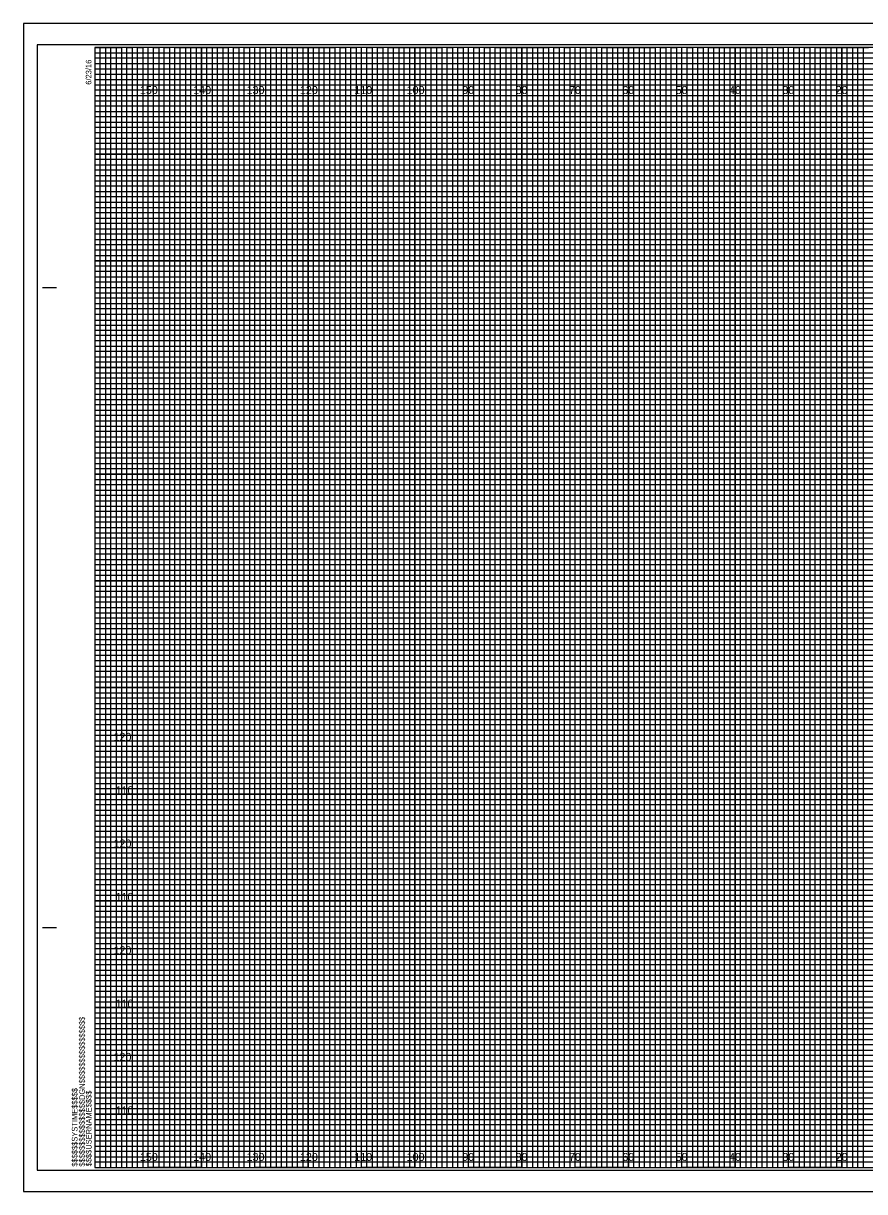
# Model space of a CAD drawing. Extents: x -13 to 323, y -5 to 215.
# Drawn here: x -13.4 to 144.3, y -4.5 to 214.5 of the extents above; entities that cross this region are included whole.
import ezdxf

# ---------------------------------------------------------------- set-up
doc = ezdxf.new("R2010")
doc.units = 0
for name, color, linetype in [('Prop XS Elevation Labels', 7, 'Continuous'), ('Prop XS Offset Labels', 7, 'Continuous'), ('Sheet Cross Section CELL', 7, 'Continuous'), ('Sheet Cross Section Grid Major CELL', 7, 'Continuous'), ('Sheet Cross Section Grid Middle CELL', 7, 'Continuous'), ('Sheet Cross Section Grid Minor 1 CELL', 7, 'Continuous'), ('Sheet Cross Section Grid Minor 2 CELL', 7, 'Continuous'), ('Sheet Cutting Line CELL', 7, 'Continuous'), ('Sheet DOT Grid CELL', 7, 'Continuous'), ('Sheet Plot Border Inside CELL', 7, 'Continuous'), ('Sheet Plot Border Outside CELL', 7, 'Continuous')]:
    doc.layers.add(name, color=color, linetype=linetype)

msp = doc.modelspace()

# ---------------------------------------------------------------- linework, layer by layer
at = {"layer": 'Sheet Cross Section CELL'}
for p, q in [((-9.8, 165), (-7.3, 165)), ((-9.7, 165), (-7.2, 165)), ((-9.8, 45), (-7.3, 45)), ((-9.7, 45), (-7.2, 45)), ((0, 0), (0, 0)), ((0, 0), (0, 0)), ((0, 0), (0, 0)), ((0, 0), (0, 0)), ((0, 0), (0, 0)), ((0, 0), (0, 0)), ((0, 0), (0, 0))]:
    msp.add_line(p, q, dxfattribs=at)
msp.add_lwpolyline([(320, 210), (0, 210), (0, 0), (320, 0)], close=True, dxfattribs=at)
at = {"layer": 'Sheet Cross Section Grid Major CELL'}
for p, q in [((10, 210), (0, 210)), ((10, 0), (10, 210)), ((30, 210), (20, 210)), ((20, 210), (20, 0)), ((30, 0), (30, 210)), ((50, 210), (40, 210)), ((40, 210), (40, 0)), ((50, 0), (50, 210)), ((70, 210), (60, 210)), ((60, 210), (60, 0)), ((70, 0), (70, 210)), ((90, 210), (80, 210)), ((80, 210), (80, 0)), ((90, 0), (90, 210)), ((110, 210), (100, 210)), ((100, 210), (100, 0)), ((110, 0), (110, 210)), ((130, 210), (120, 210)), ((120, 210), (120, 0)), ((130, 0), (130, 210)), ((150, 210), (140, 210)), ((140, 210), (140, 0)), ((20, 0), (10, 0)), ((40, 0), (30, 0)), ((60, 0), (50, 0)), ((80, 0), (70, 0)), ((100, 0), (90, 0)), ((120, 0), (110, 0)), ((140, 0), (130, 0))]:
    msp.add_line(p, q, dxfattribs=at)
for points in [[(0, 200), (320, 200), (320, 190), (0, 190)], [(0, 180), (320, 180), (320, 170), (0, 170)], [(0, 160), (320, 160), (320, 150), (0, 150)], [(0, 140), (320, 140), (320, 130), (0, 130)], [(0, 120), (320, 120), (320, 110), (0, 110)], [(0, 100), (320, 100), (320, 90), (0, 90)], [(0, 80), (320, 80), (320, 70), (0, 70)], [(0, 60), (320, 60), (320, 50), (0, 50)], [(0, 40), (320, 40), (320, 30), (0, 30)], [(0, 20), (320, 20), (320, 10), (0, 10)]]:
    msp.add_lwpolyline(points, dxfattribs=at)
at = {"layer": 'Sheet Cross Section Grid Middle CELL'}
for points in [[(0, 210), (5, 210), (5, 0), (15, 0), (15, 210), (25, 210), (25, 0), (35, 0), (35, 210), (45, 210), (45, 0), (55, 0), (55, 210), (65, 210), (65, 0), (75, 0), (75, 210), (85, 210), (85, 0), (95, 0), (95, 210), (105, 210), (105, 0), (115, 0), (115, 210), (125, 210), (125, 0), (135, 0), (135, 210), (145, 210)], [(0, 205), (275, 205)], [(0, 185), (320, 185), (320, 195), (0, 195)], [(0, 165), (320, 165), (320, 175), (0, 175)], [(0, 145), (320, 145), (320, 155), (0, 155)], [(0, 125), (320, 125), (320, 135), (0, 135)], [(0, 105), (320, 105), (320, 115), (0, 115)], [(0, 85), (320, 85), (320, 95), (0, 95)], [(0, 65), (320, 65), (320, 75), (0, 75)], [(0, 45), (320, 45), (320, 55), (0, 55)], [(0, 25), (320, 25), (320, 35), (0, 35)], [(0, 5), (320, 5), (320, 15), (0, 15)]]:
    msp.add_lwpolyline(points, dxfattribs=at)
at = {"layer": 'Sheet Cross Section Grid Minor 1 CELL'}
for p, q in [((0, 209), (260, 209)), ((260, 207.98), (0, 207.98)), ((0, 207.98), (0, 207)), ((0, 207), (260, 207)), ((260, 205.89), (0, 205.89)), ((0, 205.89), (0, 204)), ((0, 204), (320, 204))]:
    msp.add_line(p, q, dxfattribs=at)
for points in [[(0, 203), (270, 203), (320, 203), (320, 202), (0, 202)], [(0, 201), (320, 201), (320, 199), (0, 199)], [(0, 198), (320, 198), (320, 197), (0, 196.98)], [(0, 196), (320, 196), (320, 194), (0, 194)], [(0, 193), (320, 193), (320, 192), (0, 192)], [(0, 191), (320, 191), (320, 189), (0, 189)], [(0, 188), (320, 188), (320, 187), (0, 187)], [(0, 186), (320, 186), (320, 184), (0, 184)], [(0, 183), (320, 183), (320, 182), (0, 182)], [(0, 181), (320, 181), (320, 179), (0, 179)], [(0, 178), (320, 178), (320, 177), (0, 177)], [(0, 176), (320, 176), (320, 173.95), (320, 173), (320, 172), (0, 172)], [(0, 174), (320, 174), (320, 173), (0, 173)], [(0, 171), (320, 171), (320, 169), (0, 169.03)], [(0, 169.03), (320, 169), (320, 168), (0, 168)], [(0, 167), (320, 167), (320, 166), (0, 166)], [(0, 164), (320, 164), (320, 163), (0, 163)], [(0, 162), (320, 162), (320, 161), (0, 161)], [(-0.07, 158.89), (320, 158.89), (320, 157.88), (-0.07, 157.88)], [(0, 157), (320, 157), (320, 156), (0, 156)], [(0, 154), (320, 154), (320, 153), (0, 153)], [(0, 152), (320, 152), (320, 151), (0, 151)], [(0, 149), (320, 149), (320, 148), (0, 148)], [(0, 147), (320, 147), (320, 146), (0, 146)], [(0, 144), (320, 144), (320, 143), (0, 143)], [(0, 142), (320, 142), (320, 141), (0, 141)], [(0, 139), (320, 139), (319.99, 137.98), (0, 138)], [(0, 137), (320, 137), (320, 136), (0, 136)], [(0, 134), (320, 134), (320, 133), (0, 133)], [(0, 132), (320, 132), (320, 131), (0, 131)], [(0, 129), (320, 129), (320, 128), (0, 128)], [(0, 127), (320, 127), (320, 126), (0, 126)], [(0, 124), (320, 124), (320, 123), (0, 123)], [(0, 122), (320, 122), (320, 121), (0, 121)], [(0, 119), (320, 119), (320, 118), (0, 118)], [(0, 116.99), (320.07, 116.91), (320, 116), (0, 116)], [(0, 114), (320, 114), (320, 113), (0, 113)], [(0, 112), (320, 112), (320, 111), (0, 111)], [(0, 109), (320, 109), (320, 108), (0, 108)], [(0, 107), (320, 107), (320, 106), (0, 106)], [(0, 104), (320, 104), (320, 103), (0, 103)], [(0, 102), (320, 102), (320, 101), (0, 101)], [(0, 99), (320, 99), (320, 98), (0, 98)], [(0, 97), (320, 97), (320, 96), (0, 96)], [(0, 94), (320, 94), (320, 93), (0, 93)], [(0, 92), (320, 92), (320, 91), (0, 91)], [(0, 89), (320, 89), (320, 88), (0, 88)], [(0, 87), (320, 87), (320, 86), (0, 86)], [(0, 84), (320, 84), (320, 83), (0, 83)], [(0, 82), (320, 82), (320, 81), (0, 81)], [(0, 79), (320, 79), (319.99, 77.98), (0, 78)], [(0, 77), (320, 77), (320, 76), (0, 76)], [(0, 74), (320, 74), (320, 73), (0, 73)], [(0, 72), (320, 72), (320, 71), (0, 71)], [(0, 69), (320, 69), (320, 68), (0, 68)], [(0, 67), (320, 67), (320, 66), (0, 66)], [(0, 64), (320, 64), (320, 63), (0, 63)], [(0, 62), (320, 62), (320, 61), (0, 61)], [(0, 59), (320, 59), (320, 58), (0, 58)], [(0, 56.99), (320.07, 56.91), (320, 56), (0, 56)], [(0, 54), (320, 54), (320, 53), (0, 53)], [(0, 52), (320, 52), (320, 51), (0, 51)], [(0, 49), (320, 49), (320, 48), (0, 48)], [(0, 47), (320, 47), (320, 46), (0, 46)], [(0, 44), (320, 44), (320, 43), (0, 43)], [(0, 42), (320, 42), (320, 41), (0, 41)], [(0, 39), (320, 39), (320, 38), (0, 38)], [(0, 37), (320, 37), (320, 36), (0, 36)], [(0, 34), (320, 34), (320, 33), (0, 33)], [(0, 32), (320, 32), (320, 31), (0, 31)], [(0, 29), (320, 29), (320, 28), (0, 28)], [(0, 27), (320, 27), (320, 26), (0, 26)], [(0, 24), (320, 24), (320, 23), (0, 23)], [(0, 22), (320, 22), (320, 21), (0, 21)], [(0, 19), (320, 19), (320, 18), (0, 18)], [(0, 17), (320, 17), (320, 16), (0, 16)], [(0, 14), (320, 14), (320, 13), (0, 13)], [(0, 12), (320, 12), (320, 11), (0, 11)], [(0, 9), (320, 9), (320, 8), (0, 8)], [(0, 7), (320, 7), (320, 6), (0, 6)], [(0, 4), (320, 4), (320, 3), (0, 3)], [(0, 2), (320, 2), (320, 1), (0, 1)]]:
    msp.add_lwpolyline(points, dxfattribs=at)
at = {"layer": 'Sheet Cross Section Grid Minor 2 CELL'}
for points in [[(0, 0), (1, 0), (1, 210), (2, 210), (2, 0)], [(2, 0), (3, 0), (3, 210), (4, 210), (4, 0)], [(5, 0), (6, 0), (6, 210), (7, 210), (7, 0)], [(7, 0), (8, 0), (8, 210), (9, 210), (9, 0)], [(10, 0), (11, 0), (11, 210), (12, 210), (12, 0)], [(12, 0), (13, 0), (13, 210), (14, 210), (14, 0)], [(15, 0), (16, 0), (16, 210), (17, 210), (17, 0)], [(17, 0), (18, 0), (18, 210), (19, 210), (19, 0)], [(20, 0), (21, 0), (21, 210), (22, 210), (22, 0)], [(22, 0), (23, 0), (23, 210), (24, 210), (24, 0)], [(25, 0), (26, 0), (26, 210), (27, 210), (27, 0)], [(27, 0), (28, 0), (28, 210), (29, 210), (29, 0)], [(30, 0), (31, 0), (31, 210), (32, 210), (32, 0)], [(32, 0), (33, 0), (33, 210), (34, 210), (34, 0)], [(35, 0), (36, 0), (36, 210), (37, 210), (37, 0)], [(37, 0), (38, 0), (38, 210), (39, 210), (39, 0)], [(40, 0), (41, 0), (41, 210), (42, 210), (42, 0)], [(42, 0), (43, 0), (43, 210), (44, 210), (44, 0)], [(45, 0), (46, 0), (46, 210), (47, 210), (47, 0)], [(47, 0), (48, 0), (48, 210), (49, 210), (49, 0)], [(50, 0), (51, 0), (51, 210), (52, 210), (52, 0)], [(52, 0), (53, 0), (53, 210), (54, 210), (54, 0)], [(55, 0), (56, 0), (56, 210), (57, 210), (57, 0)], [(57, 0), (58, 0), (58, 210), (59, 210), (59, 0)], [(60, 0), (61, 0), (61, 210), (62, 210), (62, 0)], [(62, 0), (63, 0), (63, 210), (64, 210), (64, 0)], [(65, 0), (66, 0), (66, 210), (67, 210), (67, 0)], [(67, 0), (68, 0), (68, 210), (69, 210), (69, 0)], [(70, 0), (71, 0), (71, 210), (72, 210), (72, 0)], [(72, 0), (73, 0), (73, 210), (74, 210), (74, 0)], [(75, 0), (76, 0), (76, 210), (77, 210), (77, 0)], [(77, 0), (78, 0), (78, 210), (79, 210), (79, 0)], [(80, 0), (81, 0), (81, 210), (82, 210), (82, 0)], [(82, 0), (83, 0), (83, 210), (84, 210), (84, 0)], [(85, 0), (86, 0), (86, 210), (87, 210), (87, 0)], [(87, 0), (88, 0), (88, 210), (89, 210), (89, 0)], [(90, 0), (91, 0), (91, 210), (92, 210), (92, 0)], [(92, 0), (93, 0), (93, 210), (94, 210), (94, 0)], [(95, 0), (96, 0), (96, 210), (97, 210), (97, 0)], [(97, 0), (98, 0), (98, 210), (99, 210), (99, 0)], [(100, 0), (101, 0), (101, 210), (102, 210), (102, 0)], [(102, 0), (103, 0), (103, 210), (104, 210), (104, 0)], [(105, 0), (106, 0), (106, 210), (107, 210), (107, 0)], [(107, 0), (108, 0), (108, 210), (109, 210), (109, 0)], [(110, 0), (111, 0), (111, 210), (112, 210), (112, 0)], [(112, 0), (113, 0), (113, 210), (114, 210), (114, 0)], [(115, 0), (116, 0), (116, 210), (117, 210), (117, 0)], [(117, 0), (118, 0), (118, 210), (119, 210), (119, 0)], [(120, 0), (121, 0), (121, 210), (122, 210), (122, 0)], [(122, 0), (123, 0), (123, 210), (124, 210), (124, 0)], [(125, 0), (126, 0), (126, 210), (127, 210), (127, 0)], [(127, 0), (128, 0), (128, 210), (129, 210), (129, 0)], [(130, 0), (131, 0), (131, 210), (132, 210), (132, 0)], [(132, 0), (133, 0), (133, 210), (134, 210), (134, 0)], [(135, 0), (136, 0), (136, 210), (137, 210), (137, 0)], [(137, 0), (138, 0), (138, 210), (139, 210), (139, 0)], [(140, 0), (141, 0), (141, 210), (142, 210), (142, 0)], [(142, 0), (143, 0), (143, 210), (144, 210), (144, 0)]]:
    msp.add_lwpolyline(points, dxfattribs=at)
at = {"layer": 'Sheet Cutting Line CELL'}
for p, q in [((323.3, 214.5), (-13.4, 214.5)), ((-13.4, 214.5), (-13.4, -4.5)), ((-13.4, -4.5), (323.3, -4.5))]:
    msp.add_line(p, q, dxfattribs=at)
at = {"layer": 'Sheet DOT Grid CELL'}
for p, q in [((10, 0), (10, 210)), ((20, 0), (20, 210)), ((30, 0), (30, 210)), ((40, 0), (40, 210)), ((50, 0), (50, 210)), ((60, 0), (60, 210)), ((70, 0), (70, 210)), ((80, 0), (80, 210)), ((90, 0), (90, 210)), ((100, 0), (100, 210)), ((110, 0), (110, 210)), ((120, 0), (120, 210)), ((130, 0), (130, 210)), ((140, 0), (140, 210)), ((0, 200), (320, 200)), ((0, 190), (320, 190)), ((0, 180), (320, 180)), ((0, 170), (320, 170)), ((0, 160), (320, 160)), ((0, 150), (320, 150)), ((0, 140), (320, 140)), ((0, 130), (320, 130)), ((0, 120), (320, 120)), ((0, 110), (320, 110)), ((0, 100), (320, 100)), ((0, 90), (320, 90)), ((0, 80), (320, 80)), ((0, 70), (320, 70)), ((0, 60), (320, 60)), ((0, 50), (320, 50)), ((0, 40), (320, 40)), ((0, 30), (320, 30)), ((0, 20), (320, 20)), ((0, 10), (320, 10))]:
    msp.add_line(p, q, dxfattribs=at)
at = {"layer": 'Sheet Plot Border Inside CELL'}
msp.add_lwpolyline([(-10.8, -0.5), (322.4, -0.5), (322.4, 210.5), (-10.8, 210.5)], close=True, dxfattribs=at)
at = {"layer": 'Sheet Plot Border Outside CELL'}
msp.add_lwpolyline([(-13.4, -4.5), (323.3, -4.5), (323.3, 214.5), (-13.4, 214.5)], close=True, dxfattribs=at)

# ---------------------------------------------------------------- texts
at = {"layer": 'Prop XS Elevation Labels'}
for s, p in [('120', (3.5, 80)), ('110', (3.88, 70)), ('120', (3.5, 60)), ('110', (3.88, 50)), ('120', (3.5, 40)), ('110', (3.88, 30)), ('120', (3.5, 20)), ('110', (3.88, 10))]:
    msp.add_text(s, height=1.5, dxfattribs=at).set_placement(p)
at = {"layer": 'Prop XS Offset Labels'}
for s, p in [('150', (8.44, 201.25)), ('140', (18.44, 201.25)), ('130', (28.44, 201.25)), ('120', (38.44, 201.25)), ('110', (48.62, 201.25)), ('100', (58.44, 201.25)), ('90', (68.86, 201.25)), ('80', (78.86, 201.25)), ('70', (88.86, 201.25)), ('60', (98.86, 201.25)), ('50', (108.86, 201.25)), ('40', (118.86, 201.25)), ('30', (128.86, 201.25)), ('20', (138.86, 201.25)), ('150', (8.44, 1.25)), ('140', (18.44, 1.25)), ('130', (28.44, 1.25)), ('120', (38.44, 1.25)), ('110', (48.62, 1.25)), ('100', (58.44, 1.25)), ('90', (68.86, 1.25)), ('80', (78.86, 1.25)), ('70', (88.86, 1.25)), ('60', (98.86, 1.25)), ('50', (108.86, 1.25)), ('40', (118.86, 1.25)), ('30', (128.86, 1.25)), ('20', (138.86, 1.25))]:
    msp.add_text(s, height=1.5, dxfattribs=at).set_placement(p)
at = {"layer": 'Sheet Cross Section CELL'}
for s, p in [('6/23/16', (-0.65, 203)), ('$$$$$$$$$$$$$$$$DGN$$$$$$$$$$$$$$$$', (-1.88, 0.18)), ('$$$$$$SYSTIME$$$$$', (-3.26, 0.18)), ('$$$$USERNAME$$$$', (-0.62, 0.23))]:
    msp.add_text(s, height=1.05, rotation=90, dxfattribs=at).set_placement(p)

doc.saveas('drawing.dxf')
